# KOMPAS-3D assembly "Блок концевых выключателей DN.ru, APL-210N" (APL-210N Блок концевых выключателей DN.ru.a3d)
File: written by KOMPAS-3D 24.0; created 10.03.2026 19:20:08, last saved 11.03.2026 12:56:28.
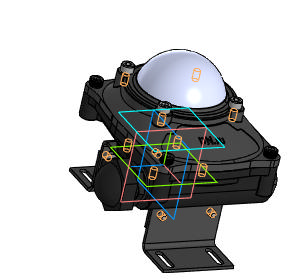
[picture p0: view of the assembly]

Document properties: Автор: R2D2; Полное имя файла: E:\Работа\Зайцев\БКВ APL-210N Блок концевых выключателей DN.ru\исходные материалы\APL-210N Блок концевых выключателей DN.ru.a3d

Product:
- Component [detail]: APL-210N-V24.08  | qty 1  | pos. 1  | Масса: 0.673493; Автор: R2D2; source file: БКВ APL-210N APL-210N.m3d
- Component [standard]: Hexagon socket head cap screw ISO 4762 - М5 x 10  | qty 8  | Материал: Не определено (density 0 kg/m3); Масса: 0.0027; Раздел спецификации: Стандартные изделия; Рассекать на разрезах: no
- Component [detail]: Деталь  | qty 2  | pos. 2  | Масса: 0.031984; Автор: R2D2; source file: Деталь.m3d
- Component [detail]: Деталь  | qty 2  | pos. 3  | Масса: 0.040625; Автор: R2D2; source file: Деталь1.m3d
- Component [standard]: Hexagon socket head cap screw ISO 4762 - М5 x 8  | qty 4  | Материал: Не определено (density 0 kg/m3); Масса: 0.00245; Раздел спецификации: Стандартные изделия; Рассекать на разрезах: no
- Component [detail]: Деталь  | qty 1  | pos. 4  | Масса: 0.143875; Автор: R2D2; source file: Деталь2.m3d
- Part/product: Блок концевых выключателей DN.ru  | designation APL-210N
    Масса: 0.22
    Раздел спецификации: Прочие изделия
    Примечание: D290-00322

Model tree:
1. Массив по концентрической сетке:1  (4 pattern instances)
     Шаг 2 = 360
2. Смещенная плоскость:1
     Расстояние = 25
3. Эскиз:2
4. Элемент выдавливания:2  (with: Грань.Элемент выдавливания:4, Грань.Листовое тело:1, Грань.Элемент выдавливания:1, Грань.Элемент вращения:1)  (labels: Грань.Элемент выдавливания:1.Экземпляр ( 2 ))
     Расстояние 1 = 18.9332; Смещение 1 = 0.5; Расстояние = -35; Расстояние = -40; Ориентация = 2; Ориентация = 2; Ориентация = 2; Ориентация = 2; Ориентация = 2; Ориентация = 2; Расстояние = 3

Referenced files in E:\Работа\Зайцев\БКВ APL-210N Блок концевых выключателей DN.ru\исходные материалы\: БКВ APL-210N APL-210N.m3d, Деталь.m3d, Деталь1.m3d, Деталь2.m3d
Referenced files in C:\Program Files\ASCON\KOMPAS-3D v24\Libs\PolynomLib\DATA\vault\Methods\Kompas\3D\: PLib_Screw_DIN_7984_1500.m3d
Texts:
  Hexagon socket head cap screw
  BOSimple***PART:21ed9b3c-5d08-71a9-dbcb-7277ad8540f3***SHORTLOC:A259_235BDFABBEFC4171[0,8;10;5;-;Undefined]
  BOSimple***PART:2d8c9a95-15dc-3e7c-f94e-4ac000f9c72a***SHORTLOC:A259_235BDFABBEFC4171[0,8;8;5;-;Undefined]
  Программные изделия  и базы данных
  APL-210N
  APL-210N-V24.08 APL-210N-V24.08
  Hexagon socket head cap screw ISO 4762 - М5 x 10 (1)
  Деталь (1)
  Hexagon socket head cap screw ISO 4762 - М5 x 10 (2)
  Hexagon socket head cap screw ISO 4762 - М5 x 10 (3)
  Hexagon socket head cap screw ISO 4762 - М5 x 8 (1)
  Hexagon socket head cap screw ISO 4762 - М5 x 8 (2)
  Деталь (2)
  Hexagon socket head cap screw ISO 4762 - М5 x 8 (3)
  Hexagon socket head cap screw ISO 4762 - М5 x 8 (4)
  Hexagon socket head cap screw ISO 4762 - М5 x 10 (7)
  Hexagon socket head cap screw ISO 4762 - М5 x 10 (8)
  Плоскость ZX.Начало координат
  Ось Y.Начало координат
  Плоскость ZY.Начало координат
  Плоскость XY.Начало координат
